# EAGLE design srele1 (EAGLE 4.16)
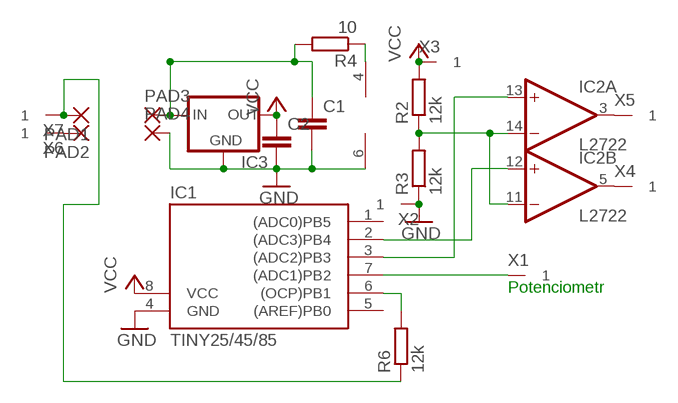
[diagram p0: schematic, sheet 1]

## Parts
C1  C-EU025-024X044  [C025-024X044]
C2  C-EU025-024X044  [C025-024X044]
IC1  TINY25/45/85  TINY15LP  [DIL08]
IC2  L2722  [SO16]
IC3  78LXX  [78LXX]
PAD1  SMD2  [SMD1,27-2,54]
PAD2  SMD2  [SMD1,27-2,54]
PAD3  SMD2  [SMD1,27-2,54]
PAD4  SMD2  [SMD1,27-2,54]
R2  12k  R-EU_0204/5  [0204/5]
R3  12k  R-EU_0204/5  [0204/5]
R4  10  R-EU_0207/10  [0207/10]
R6  12k  R-EU_0204/7  [0204/7]
X1  PAD-Y-ASYM  [Y_LONG_ASYM]
X2  PAD-Y-ASYM  [Y_LONG_ASYM]
X3  PAD-Y-ASYM  [Y_LONG_ASYM]
X4  PAD-Y-ASYM  [Y_LONG_ASYM]
X5  PAD-Y-ASYM  [Y_LONG_ASYM]
X6  PAD-Y-ASYM  [Y_LONG_ASYM]
X7  PAD-Y-ASYM  [Y_LONG_ASYM]

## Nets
GND: C1.2 C2.2 IC1.4(GND) IC2.6(P:GND) IC3.GND PAD4.1(P) R3.1 X2.A1
N$1: IC2.11(B:-IN) IC2.14(A:-IN) R2.1 R3.2
N$2: IC1.3((ADC2)PB3) IC2.13(A:+IN)
N$3: IC1.6((OCP)PB1) R6.2
N$4: IC1.2((ADC3)PB4) IC2.12(B:+IN)
N$5: PAD1.1(P) R6.1 X7.A1
N$6: IC2.5(B:OUT) X4.A1
N$7: IC2.3(A:OUT) X5.A1
N$9: IC2.4(P:V+) R4.1
N$11: C1.1 IC3.IN PAD3.1(P) R4.2
N$12: IC1.7((ADC1)PB2) X1.A1
N$13: PAD2.1(P) X6.A1
VCC: C2.1 IC1.8(VCC) IC3.OUT R2.2 X3.A1
Unconnected: IC1.1((ADC0)PB5) IC1.5((AREF)PB0)

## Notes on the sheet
- Potenciometr

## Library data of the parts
C1 C2 = RCL:C-EU: CAPACITOR, European symbol
IC1 = atmel-1:TINY15L: MICROCONTROLLER 2.7 V 1 Kbytes FLASH 64 bytes EEPROM 4-channel 10 bit ADC
IC2 = LINEAR:L2722: OP AMP
IC3 = v-reg:78LXX: VOLTAGE REGULATOR
PAD1-PAD4 = wirepad:SMD2: SMD PAD
R2-R4 R6 = RCL:R-EU_: RESISTOR, European symbol
X1-X7 = special-pad:PAD-Y-ASYM: Y Long asymetrical Pad

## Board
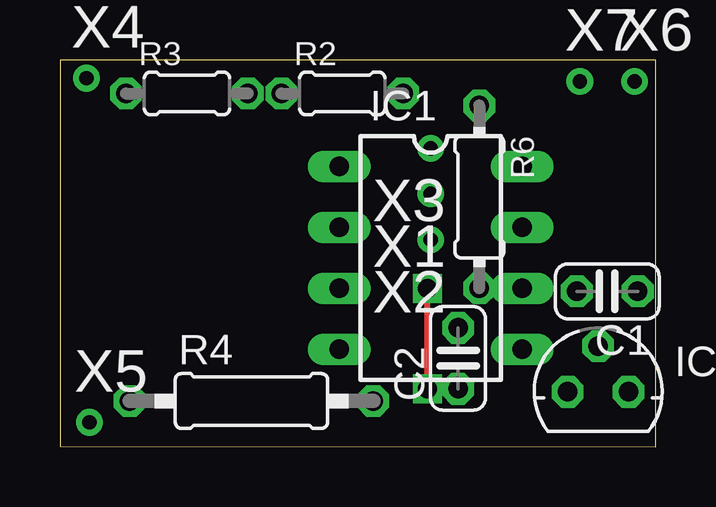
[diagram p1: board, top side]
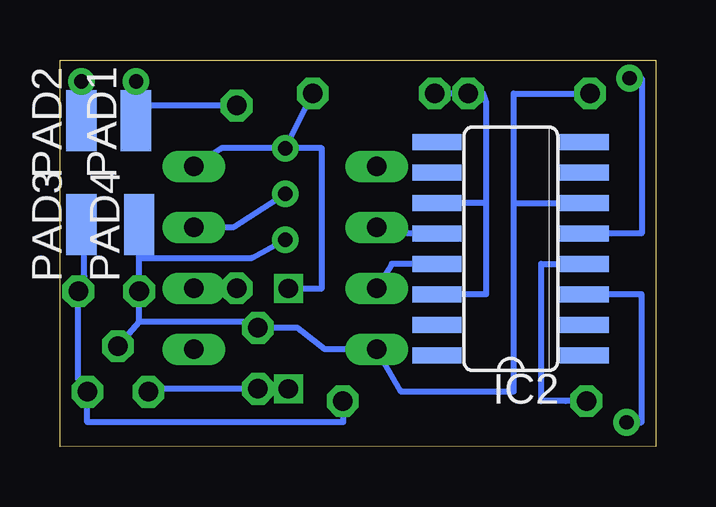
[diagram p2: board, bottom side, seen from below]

Size 24.85 x 16.13 mm. Coordinates in mm from the lower left corner, seen from the top.
Outline: 24.85,0 24.85,16.13 0,16.12 0,0.01 24.85,0
Copper layers (1*16): Top 0.035mm / dielectric 1.5mm / Bottom 0.035mm
Design rules "default": minimum track width 10mil, minimum drill 24mil, track to track 8mil, track to pad 8mil, pad to pad 8mil, via to via 8mil, smd to smd 8mil, copper to edge 40mil, drill to drill 8mil, minimum pad ring 10mil, minimum via ring 8mil, stop-mask expansion 4mil, vias tented up to drill 0mil, thermal gap 10mil

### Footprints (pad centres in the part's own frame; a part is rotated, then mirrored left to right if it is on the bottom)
C025-024X044 = drill 0.813 octagon: 1 -1.27,0; 2 1.27,0
DIL08 = drill 0.813 long: 1 -3.81,-3.81; 2 -1.27,-3.81; 3 1.27,-3.81; 4 3.81,-3.81; 5 3.81,3.81; 6 1.27,3.81; 7 -1.27,3.81; 8 -3.81,3.81
SO16 = smd 0.66 x 2.032: 1 -4.445,-3.073; 2 -3.175,-3.073; 3 -1.905,-3.073; 4 -0.635,-3.073; 5 0.635,-3.073; 6 1.905,-3.073; 7 3.175,-3.073; 8 4.445,-3.073; 9 4.445,3.073; 10 3.175,3.073; 11 1.905,3.073; 12 0.635,3.073; 13 -0.635,3.073; 14 -1.905,3.073; 15 -3.175,3.073; 16 -4.445,3.073
78LXX = drill 0.813 octagon: GND 0,1.905; IN 1.27,0; OUT -1.27,0
SMD1,27-2,54 = smd 1.27 x 2.54: 1 0,0
0204/5 = drill 0.813 octagon: 1 -2.54,0; 2 2.54,0
0207/10 = drill 0.813 octagon: 1 -5.08,0; 2 5.08,0
0204/7 = drill 0.813 octagon: 1 -3.81,0; 2 3.81,0
Y_LONG_ASYM = drill 0.6 round: A1 0,0

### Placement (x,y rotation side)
C1  22.82,6.48 180 top
C2  16.6,3.68 90 top
IC1  15.46,7.87 270 top
IC2  6.06,8.26 90 bottom
IC3  22.44,2.29 0 top
PAD1  21.68,13.59 0 bottom
PAD2  23.96,13.59 0 bottom
PAD3  23.96,9.27 0 bottom
PAD4  21.55,9.27 0 bottom
R2  11.77,14.73 0 top
R3  5.3,14.73 0 top
R4  7.98,1.9 0 top
R6  17.49,10.41 270 top
X1  15.46,10.54 180 top
X2  15.46,8.64 180 top
X3  15.46,12.45 180 top
X4  1.1,15.37 0 top
X5  1.23,1.02 0 top
X6  23.96,15.24 0 top
X7  21.68,15.24 0 top

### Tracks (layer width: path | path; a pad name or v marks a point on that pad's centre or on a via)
GND
  Bottom 0.254: 21.55,7.87 16.85,7.87 X2.A1 | 21.55,7.87 C1.2 21.55,5.21 | 21.55,7.87 PAD4.1 | 21.55,5.21 IC3.GND | 5.93,10.16 5.93,14.73 R3.1 | 5.93,10.16 5.93,2.29 10.63,2.29 IC1.4 13.8,4.06 14.95,4.95 C2.2 17.23,5.21 21.55,5.21 | 5.93,10.16 IC2.6
N$1
  Bottom 0.254: 7.07,10.16 7.07,6.35 IC2.14 | 7.07,10.16 IC2.11 | R2.1 R3.2 7.2,14.73 7.07,14.35 7.07,10.16
N$2
  Bottom 0.254: IC2.13 11.01,7.62 IC1.3
N$3
  Bottom 0.254: R6.2 IC1.6
N$4
  Bottom 0.254: IC2.12 10.38,8.89 IC1.2
N$5
  Bottom 0.254: X7.A1 21.81,14.99 21.81,14.73 PAD1.1 21.3,14.22 R6.1
N$6
  Bottom 0.254: X4.A1 0.6,15.37 0.6,8.89 IC2.5
N$7
  Bottom 0.254: X5.A1 0.6,1.02 0.6,6.35 IC2.3
N$9
  Bottom 0.254: IC2.4 4.79,7.62 4.79,1.91 3.77,1.91 R4.1
N$11
  Bottom 0.254: PAD3.1 23.84,8.13 23.84,7.11 C1.1 24.09,2.79 IC3.IN 23.71,1.02 13.04,1.02 R4.2
N$12
  Bottom 0.254: X1.A1 17.61,9.14 IC1.7
N$13
  Bottom 0.254: X6.A1 23.84,14.99 23.84,14.73 PAD2.1
VCC  (via drill 0.8)
  Top 0.254: v15.33,2.41 v15.33,6.6
  Bottom 0.254: IC3.OUT 20.54,2.41 C2.1 v15.33,2.41 | X3.A1 R2.2 X3.A1 | 13.93,12.45 18.12,12.45 IC1.8 | 13.93,12.45 X3.A1 | v15.33,6.6 13.93,6.6 13.93,12.45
